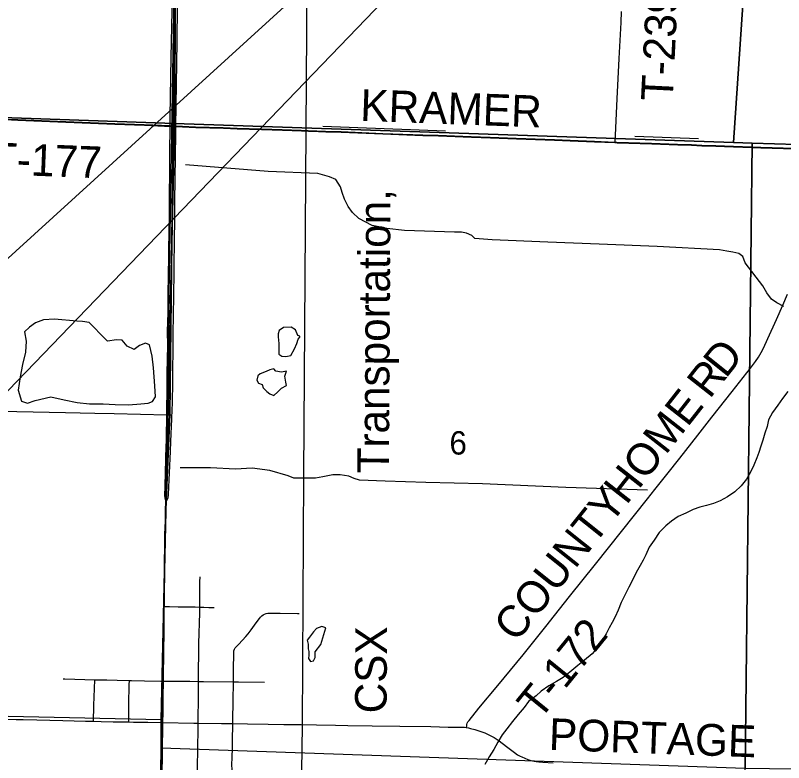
# Model space of a CAD drawing. Extents: x -59 to 43, y 0 to 22.
# Drawn here: x 24.882 to 26.258, y 14.155 to 15.494 of the extents above; entities that cross this region are included whole.
import ezdxf

# ---------------------------------------------------------------- set-up
doc = ezdxf.new("R2010")
doc.units = 0
for name, color, linetype in [('BR_P_Gen_Text', 7, 'Continuous'), ('Default', 7, 'Continuous'), ('GM_X_City_Street', 7, 'Continuous'), ('GM_X_Interchange_Ramps', 7, 'Continuous'), ('GM_X_Major_River', 7, 'Continuous'), ('GM_X_Minor_Lake', 7, 'Continuous'), ('GM_X_Minor_River', 7, 'Continuous'), ('GM_X_Rail_Line', 7, 'Continuous'), ('GM_X_Rail_Line_Text', 7, 'Continuous'), ('GM_X_Section', 7, 'Continuous'), ('GM_X_Section_Text', 7, 'Continuous'), ('GM_X_State_Route', 7, 'Continuous'), ('GM_X_Township_Road', 7, 'Continuous'), ('GM_X_Township_Road_Text', 7, 'Continuous')]:
    doc.layers.add(name, color=color, linetype=linetype)

msp = doc.modelspace()

# ---------------------------------------------------------------- linework, layer by layer
at = {"layer": 'BR_P_Gen_Text'}
msp.add_lwpolyline([(26.7273, 16.7521), (23.5585, 13.8664), (23.9482, 13.8664)], close=True, dxfattribs=at)
at = {"layer": 'Default'}
for points in [[(24.127, 14.1), (25.1417, 14.1), (25.1429, 14.1814), (25.1432, 14.2318), (24.1287, 14.2542)], [(25.1417, 14.1), (26.1878, 14.1), (26.1894, 14.1445), (25.1429, 14.1814)]]:
    msp.add_lwpolyline(points, close=True, dxfattribs=at)
at = {"layer": 'GM_X_City_Street'}
for points in [[(25.2095, 14.2261), (25.2095, 14.2286), (25.2094, 14.2365), (25.2096, 14.2485), (25.2097, 14.2548), (25.2098, 14.2625), (25.2099, 14.2686), (25.2099, 14.277), (25.2099, 14.2886), (25.2099, 14.2928), (25.21, 14.3008), (25.21, 14.3074), (25.2101, 14.3156), (25.2102, 14.3261), (25.2107, 14.3447), (25.2107, 14.3508), (25.2107, 14.3601), (25.2108, 14.3629), (25.2108, 14.3688), (25.2121, 14.4237), (25.2121, 14.433), (25.2121, 14.4338), (25.2122, 14.4391), (25.2121, 14.4422), (25.2124, 14.4607), (25.2125, 14.4678), (25.2126, 14.4792), (25.2127, 14.4881)], [(25.1484, 14.4352), (25.1581, 14.4349), (25.1735, 14.4345), (25.2042, 14.4341), (25.2121, 14.4338), (25.2196, 14.4336), (25.2287, 14.4334), (25.2348, 14.4332), (25.2378, 14.433)], [(25.2712, 14.2251), (25.2713, 14.2313), (25.2718, 14.2654), (25.2725, 14.2998), (25.2729, 14.3212), (25.2732, 14.3522), (25.2734, 14.3552), (25.2742, 14.3582), (25.2758, 14.3608), (25.2779, 14.3632), (25.282, 14.3677), (25.295, 14.381), (25.2989, 14.3858), (25.3046, 14.3931), (25.3134, 14.4059), (25.319, 14.4133), (25.321, 14.4157), (25.3232, 14.4179), (25.3257, 14.4198), (25.3284, 14.4212), (25.3313, 14.4221), (25.3344, 14.4227), (25.3406, 14.423), (25.3561, 14.423), (25.3871, 14.4223), (25.3902, 14.4222)], [(24.9673, 14.3053), (24.9703, 14.3053), (25.024, 14.3037), (25.0306, 14.3036), (25.0458, 14.3034), (25.064, 14.3031), (25.0862, 14.3025), (25.0902, 14.3024), (25.113, 14.3019), (25.1422, 14.3013), (25.1469, 14.3012)], [(25.0218, 14.2293), (25.0219, 14.2338), (25.0221, 14.2399), (25.0223, 14.2461), (25.0226, 14.2583), (25.023, 14.2724), (25.0235, 14.2882), (25.024, 14.3037)], [(25.085, 14.2281), (25.085, 14.2349), (25.0852, 14.2599), (25.086, 14.2943), (25.0862, 14.3025)], [(25.1469, 14.3012), (25.1751, 14.3011), (25.1942, 14.3009), (25.21, 14.3008), (25.2191, 14.3008), (25.2725, 14.2998), (25.2816, 14.2997), (25.328, 14.2993)], [(25.2086, 14.1095), (25.2085, 14.1156), (25.2084, 14.1217), (25.2084, 14.1248), (25.2084, 14.1433), (25.2083, 14.1489), (25.2083, 14.1512), (25.2083, 14.1585), (25.2086, 14.1677), (25.2087, 14.18), (25.2088, 14.1862), (25.2089, 14.1892), (25.2093, 14.2077), (25.2095, 14.2261)], [(25.2693, 14.1), (25.2695, 14.1014), (25.2698, 14.1056), (25.2699, 14.109), (25.27, 14.116), (25.2699, 14.1315), (25.27, 14.1438), (25.2699, 14.1505), (25.2699, 14.1537), (25.2701, 14.1623), (25.2708, 14.184), (25.2709, 14.1934), (25.2712, 14.2251)]]:
    msp.add_lwpolyline(points, dxfattribs=at)
at = {"layer": 'GM_X_Interchange_Ramps'}
for points in [[(24.8519, 15.3082), (24.886, 15.3068), (24.9574, 15.3039), (25.0599, 15.2995), (25.1127, 15.2977), (25.159, 15.2958), (25.1643, 15.2956), (25.1703, 15.7035), (25.1708, 15.7575), (25.1711, 15.7752), (25.1717, 15.8181), (25.1735, 16.0497), (25.1736, 16.0538), (25.1762, 16.1201), (25.1726, 16.298), (25.1734, 16.3535), (25.1731, 16.4049), (25.1737, 16.4832), (25.1737, 16.4888), (25.1743, 16.5339), (25.1743, 16.5397), (25.1751, 16.5992)], [(25.1703, 15.7035), (25.1643, 15.2956), (25.1692, 15.2953), (25.2047, 15.2938), (25.2544, 15.2923), (25.2793, 15.2914), (25.3228, 15.2898), (25.36, 15.2888), (25.3942, 15.2875), (25.4066, 15.287), (25.4376, 15.2859), (25.4656, 15.2851), (25.5402, 15.2819), (25.6116, 15.2795), (25.6396, 15.2784), (25.6986, 15.2765), (25.7328, 15.2753), (25.7794, 15.2732), (25.8477, 15.2708), (25.8757, 15.2698), (25.9192, 15.2681), (25.9561, 15.2664), (25.9596, 15.2663), (26.0217, 15.2644), (26.0683, 15.2628), (26.0932, 15.2617), (26.1118, 15.2609), (26.1367, 15.2601), (26.1522, 15.2596), (26.2174, 15.2572), (26.2982, 15.2549)], [(25.1448, 14.1524), (25.1451, 14.1725), (25.1457, 14.2277), (25.146, 14.2445), (25.1463, 14.2724), (25.1466, 14.3017), (25.1473, 14.3594), (25.1477, 14.3843), (25.1478, 14.3968), (25.1481, 14.4309), (25.1482, 14.4357), (25.1484, 14.4464), (25.1486, 14.4697), (25.1488, 14.4847), (25.1489, 14.4962), (25.1492, 14.521), (25.1494, 14.5367), (25.1496, 14.555), (25.1498, 14.567), (25.15, 14.5741), (25.1519, 14.6238), (25.1584, 14.7789), (25.159, 14.8311), (25.1643, 15.2956), (25.159, 15.2958), (25.1127, 15.2977), (25.0599, 15.2995), (24.9574, 15.3039), (24.886, 15.3068), (24.8519, 15.3082)], [(26.2982, 15.2549), (26.2174, 15.2572), (26.1522, 15.2596), (26.1367, 15.2601), (26.1118, 15.2609), (26.0932, 15.2617), (26.0683, 15.2628), (26.0217, 15.2644), (25.9596, 15.2663), (25.9561, 15.2664), (25.9192, 15.2681), (25.8757, 15.2698), (25.8477, 15.2708), (25.7794, 15.2732), (25.7328, 15.2753), (25.6986, 15.2765), (25.6396, 15.2784), (25.6116, 15.2795), (25.5402, 15.2819), (25.4656, 15.2851), (25.4376, 15.2859), (25.4066, 15.287), (25.3942, 15.2875), (25.36, 15.2888), (25.3228, 15.2898), (25.2793, 15.2914), (25.2544, 15.2923), (25.2047, 15.2938), (25.1692, 15.2953), (25.1643, 15.2956), (25.159, 14.8311), (25.1584, 14.7789), (25.1519, 14.6238), (25.15, 14.5741), (25.1498, 14.567), (25.1496, 14.555), (25.1494, 14.5367), (25.1492, 14.521), (25.1489, 14.4962), (25.1488, 14.4847), (25.1486, 14.4697), (25.1484, 14.4464), (25.1482, 14.4357), (25.1481, 14.4309), (25.1478, 14.3968), (25.1477, 14.3843), (25.1473, 14.3594), (25.1466, 14.3017), (25.1463, 14.2724), (25.146, 14.2445), (25.1457, 14.2277), (25.1451, 14.1725), (25.1448, 14.1524)]]:
    msp.add_lwpolyline(points, dxfattribs=at)
at = {"layer": 'GM_X_Major_River'}
msp.add_lwpolyline([(26.266, 14.8203), (26.2561, 14.8078), (26.2477, 14.7956), (26.2385, 14.7827), (26.2313, 14.7695), (26.2286, 14.7573), (26.2248, 14.7456), (26.2209, 14.7327), (26.2175, 14.7224), (26.214, 14.7106), (26.2106, 14.7011), (26.2052, 14.6879), (26.1991, 14.6757), (26.1915, 14.6628), (26.182, 14.6511), (26.1706, 14.6405), (26.1576, 14.6314), (26.1447, 14.6242), (26.1326, 14.6193), (26.1204, 14.6159), (26.1079, 14.6126), (26.0961, 14.6084), (26.0832, 14.6024), (26.0695, 14.596), (26.0573, 14.5876), (26.0471, 14.5797), (26.0356, 14.5672), (26.0261, 14.5539), (26.0174, 14.541), (26.0112, 14.5274), (26.0067, 14.5179), (26.0013, 14.5084), (25.9944, 14.4959), (25.988, 14.4834), (25.9811, 14.4693), (25.9738, 14.4553), (25.9673, 14.442), (25.962, 14.4284), (25.9563, 14.4162), (25.9513, 14.4064), (25.946, 14.3965), (25.9402, 14.3859), (25.9326, 14.3737), (25.9265, 14.3635), (25.9155, 14.3502), (25.9014, 14.3389), (25.8896, 14.3291), (25.8755, 14.3173), (25.8633, 14.3079), (25.8512, 14.3007), (25.8375, 14.2927), (25.8242, 14.2833), (25.8147, 14.2746), (25.8014, 14.2647), (25.7937, 14.2537), (25.7827, 14.2416), (25.7724, 14.2291), (25.7625, 14.2158), (25.7541, 14.2049), (25.7465, 14.1916), (25.7389, 14.1787), (25.7309, 14.1654), (25.7232, 14.1518)], dxfattribs=at)
at = {"layer": 'GM_X_Minor_Lake'}
for p, q in [((24.9922, 14.9463), (24.952, 14.9499)), ((25.3526, 14.9179), (25.3537, 14.9058)), ((25.3312, 14.8561), (25.3205, 14.8515)), ((25.4067, 14.359), (25.4078, 14.3544))]:
    msp.add_line(p, q, dxfattribs=at)
for points in [[(24.952, 14.9499), (24.9323, 14.9484), (24.9182, 14.9431), (24.9072, 14.9352), (24.8985, 14.9272), (24.9011, 14.9101), (24.8999, 14.8908), (24.8949, 14.8687), (24.8906, 14.8463), (24.8871, 14.8224), (24.8928, 14.803), (24.9038, 14.7992), (24.9174, 14.8041), (24.9455, 14.8108), (24.9694, 14.8051), (24.9926, 14.8005), (25.0149, 14.7981), (25.0392, 14.7977), (25.0605, 14.7968), (25.0847, 14.7964), (25.1068, 14.7982), (25.1197, 14.7993), (25.1273, 14.802), (25.133, 14.8103), (25.1315, 14.8301), (25.1293, 14.8623), (25.1268, 14.8836), (25.1223, 14.9038), (25.1151, 14.9068), (25.1044, 14.9023), (25.0945, 14.8955), (25.0824, 14.9012), (25.073, 14.9119), (25.0631, 14.9127), (25.0468, 14.9105), (25.0358, 14.9215), (25.0218, 14.936), (25.0139, 14.9436), (25.0021, 14.9455), (24.9922, 14.9463)], [(25.3537, 14.9058), (25.3537, 14.9004), (25.3537, 14.8936), (25.354, 14.8871), (25.3593, 14.8833), (25.3665, 14.8825), (25.3753, 14.8844), (25.3821, 14.8966), (25.386, 14.906), (25.3883, 14.9136), (25.3917, 14.9174), (25.3917, 14.9193), (25.3879, 14.9205), (25.3838, 14.9307), (25.3758, 14.9353), (25.3625, 14.9346), (25.3545, 14.9293), (25.3526, 14.9236), (25.3526, 14.9179)], [(25.3205, 14.8515), (25.316, 14.8481), (25.3144, 14.8402), (25.3175, 14.8348), (25.3239, 14.8325), (25.3258, 14.8264), (25.3322, 14.8203), (25.3379, 14.8158), (25.3447, 14.8131), (25.3519, 14.8195), (25.3588, 14.8263), (25.3679, 14.8309), (25.3664, 14.8366), (25.3645, 14.8476), (25.3676, 14.8563), (25.3589, 14.8548), (25.3483, 14.8568), (25.3452, 14.8606), (25.338, 14.8591), (25.3312, 14.8561)], [(25.4078, 14.3544), (25.4074, 14.3476), (25.407, 14.3419), (25.4108, 14.3362), (25.4161, 14.3377), (25.4191, 14.3433), (25.4192, 14.354), (25.4291, 14.3669), (25.4379, 14.3965), (25.4311, 14.3992), (25.4212, 14.3958), (25.4163, 14.3897), (25.409, 14.3802), (25.4048, 14.3749), (25.4067, 14.3677), (25.4067, 14.359)]]:
    msp.add_lwpolyline(points, dxfattribs=at)
at = {"layer": 'GM_X_Minor_River'}
for points in [[(25.6527, 15.2863), (25.4327, 15.2949)], [(26.1057, 15.2728), (25.9919, 15.277)], [(26.2585, 14.9726), (26.2463, 14.9787), (26.2365, 14.9852), (26.2282, 14.9967), (26.221, 15.0092), (26.1897, 15.0507), (26.1855, 15.0617), (26.1783, 15.0671), (26.1673, 15.0698), (26.1563, 15.0717), (26.1434, 15.074), (26.0315, 15.08), (25.9279, 15.0841), (25.8358, 15.0878), (25.7364, 15.0915), (25.7049, 15.0939), (25.6996, 15.0996), (25.6901, 15.1035), (25.681, 15.1054), (25.6685, 15.1058), (25.579, 15.1087), (25.5472, 15.112), (25.5213, 15.1172), (25.4974, 15.1299), (25.4861, 15.1405), (25.4782, 15.1516), (25.4714, 15.1649), (25.4672, 15.1767), (25.4646, 15.1869), (25.4563, 15.1999), (25.4449, 15.2045), (25.4362, 15.2072), (25.4237, 15.2106), (25.3345, 15.2139), (25.1866, 15.2261)], [(26.0143, 14.6436), (25.8682, 14.6482), (25.7187, 14.6547), (25.6174, 14.6573), (25.5442, 14.6594), (25.4987, 14.6611), (25.4888, 14.6645), (25.4793, 14.6683), (25.4638, 14.671), (25.4509, 14.6707), (25.433, 14.6673), (25.4194, 14.6647), (25.4, 14.6648), (25.3807, 14.6648), (25.3704, 14.669), (25.3375, 14.6786), (25.3064, 14.6825), (25.2764, 14.6811), (25.2316, 14.6835), (25.1774, 14.6833)]]:
    msp.add_lwpolyline(points, dxfattribs=at)
at = {"layer": 'GM_X_Rail_Line'}
for points in [[(25.3948, 14.1), (25.3961, 14.2211), (25.3988, 14.6701), (25.4079, 15.9972), (25.4144, 16.3516), (25.419, 16.4865), (25.4235, 16.5443), (25.4371, 16.6599), (25.4762, 17.0572), (25.4837, 17.1373), (25.4914, 17.219), (25.4936, 17.2735), (25.4946, 17.3274), (25.4973, 17.5422), (25.5003, 17.9438), (25.5067, 18.4239), (25.5079, 18.556), (25.5143, 18.6352), (25.5252, 18.7035), (25.5418, 18.7744), (25.5673, 18.8657), (25.6145, 19.001)], [(25.1428, 14.1), (25.1449, 14.2295), (25.1538, 14.7802), (25.1709, 15.8209), (25.1663, 16.5615), (25.1883, 17.5646)]]:
    msp.add_lwpolyline(points, dxfattribs=at)
at = {"layer": 'GM_X_Section'}
for points in [[(24.1477, 16.3396), (25.173, 16.308), (25.1744, 16.294), (25.1667, 15.3001), (24.1557, 15.3353)], [(25.1744, 16.294), (26.2361, 16.2622), (26.1685, 15.2661), (25.1667, 15.3001)], [(26.2361, 16.2622), (27.2374, 16.2454), (27.2021, 15.2348), (26.2022, 15.2649), (26.1685, 15.2661)], [(24.1557, 15.3353), (25.1667, 15.3001), (25.1432, 14.2318), (24.1287, 14.2542)], [(25.1667, 15.3001), (26.1685, 15.2661), (26.2022, 15.2649), (26.1894, 14.1445), (25.1429, 14.1814), (25.1432, 14.2318)], [(26.2022, 15.2649), (27.2021, 15.2348), (27.2112, 15.2343), (27.188, 14.1311), (26.1894, 14.1445)]]:
    msp.add_lwpolyline(points, close=True, dxfattribs=at)
at = {"layer": 'GM_X_State_Route'}
msp.add_line((25.1532, 14.7785), (25.154, 14.8322), dxfattribs=at)
for points in [[(25.1592, 15.2952), (25.1594, 15.3126), (25.1612, 15.4182), (25.1626, 15.5021), (25.1627, 15.5301), (25.1629, 15.5394), (25.1635, 15.5609), (25.1641, 15.6138), (25.1642, 15.6293), (25.1653, 15.6821), (25.1656, 15.7008), (25.1656, 15.703)], [(25.1694, 15.2948), (25.1715, 15.4466), (25.1723, 15.5118), (25.1737, 15.6113), (25.1741, 15.6485), (25.1745, 15.6734), (25.175, 15.6951), (25.175, 15.7029)], [(25.154, 14.8322), (25.1541, 14.8371), (25.1541, 14.8527), (25.1549, 14.9024), (25.1546, 14.9273), (25.1554, 14.9614), (25.1559, 15.0049), (25.1561, 15.0173), (25.1571, 15.0733), (25.1578, 15.1385), (25.1587, 15.2473), (25.1592, 15.2952)], [(25.1637, 14.8308), (25.1642, 14.8562), (25.1643, 14.8966), (25.1648, 14.9214), (25.1654, 14.9587), (25.1657, 14.9898), (25.1662, 15.0364), (25.1672, 15.0985), (25.1676, 15.1203), (25.1678, 15.1607), (25.1692, 15.2819), (25.1694, 15.2948)], [(25.1621, 14.7712), (25.1624, 14.7783), (25.1625, 14.7808), (25.1637, 14.8308)], [(25.1522, 14.6232), (25.1539, 14.6259), (25.1554, 14.6301), (25.156, 14.6336), (25.1563, 14.6363), (25.1597, 14.7128), (25.1603, 14.7307), (25.1621, 14.7712)], [(25.1524, 14.7303), (25.1525, 14.7358), (25.1532, 14.7785)], [(25.1522, 14.6232), (25.1506, 14.6268), (25.15, 14.6296), (25.1497, 14.6333), (25.1504, 14.6505), (25.1522, 14.7232), (25.1524, 14.7303)], [(25.1481, 14.3992), (25.1483, 14.4304), (25.1484, 14.4352), (25.1486, 14.4459), (25.1489, 14.4691), (25.149, 14.4842), (25.1491, 14.4957), (25.1494, 14.5205), (25.1496, 14.5362), (25.1498, 14.5545), (25.15, 14.5664), (25.1502, 14.5736), (25.1522, 14.6232)], [(25.147, 14.3131), (25.1476, 14.3589), (25.1479, 14.3837), (25.1481, 14.3962), (25.1481, 14.3992)], [(25.1459, 14.2272), (25.1462, 14.2439), (25.1465, 14.2718), (25.1469, 14.3012), (25.147, 14.3131)], [(25.1442, 14.1), (25.1446, 14.1244), (25.1449, 14.1438), (25.145, 14.1518), (25.1453, 14.1719), (25.1459, 14.2272)]]:
    msp.add_lwpolyline(points, dxfattribs=at)
at = {"layer": 'GM_X_Township_Road'}
for p, q in [((25.1492, 15.2957), (25.1592, 15.2952)), ((25.1592, 15.2952), (25.1646, 15.295)), ((25.1646, 15.295), (25.1694, 15.2948)), ((25.1586, 14.7784), (25.1624, 14.7783))]:
    msp.add_line(p, q, dxfattribs=at)
for points in [[(25.9564, 15.2659), (25.9565, 15.2691), (25.957, 15.2795), (25.9602, 15.3442), (25.9639, 15.4168), (25.9671, 15.4814), (25.9681, 15.5007)], [(24.154, 15.3313), (24.1784, 15.3306), (24.2405, 15.3285), (24.2995, 15.3269), (24.3554, 15.3253), (24.3927, 15.3239), (24.4734, 15.3211), (24.5386, 15.3187), (24.6163, 15.3158), (24.6565, 15.3141), (24.6936, 15.313), (24.7682, 15.3106), (24.8117, 15.309), (24.8521, 15.3077), (24.8862, 15.3063), (24.9577, 15.3034), (25.0601, 15.299), (25.113, 15.2972), (25.1492, 15.2957)], [(25.1694, 15.2948), (25.2049, 15.2932), (25.2546, 15.2918), (25.2795, 15.2909), (25.323, 15.2892), (25.3603, 15.2883), (25.3944, 15.2869), (25.4068, 15.2864), (25.4118, 15.2863)], [(25.4118, 15.2863), (25.4379, 15.2854), (25.4658, 15.2845), (25.5404, 15.2814), (25.6119, 15.2789), (25.6398, 15.2778), (25.6989, 15.2759), (25.733, 15.2748), (25.7796, 15.2727), (25.848, 15.2703), (25.8759, 15.2692), (25.9194, 15.2675), (25.9564, 15.2659)], [(25.9564, 15.2659), (25.9598, 15.2657), (26.0219, 15.2638), (26.0686, 15.2622), (26.0934, 15.2611), (26.112, 15.2604), (26.1369, 15.2596), (26.1524, 15.2591), (26.2176, 15.2567), (26.2984, 15.2544), (26.3085, 15.2542)], [(25.6903, 14.218), (25.6905, 14.2213), (25.6908, 14.2235), (25.6915, 14.2257), (25.6928, 14.2285), (25.6947, 14.2309), (25.7124, 14.2525), (25.7461, 14.2932), (25.7916, 14.3482), (25.8325, 14.3991), (25.8478, 14.4186), (25.8746, 14.4528), (25.9213, 14.511), (25.9446, 14.54), (25.9911, 14.5983), (26.0142, 14.6275), (26.0277, 14.6445), (26.0491, 14.6712), (26.0721, 14.7005), (26.1048, 14.7419), (26.1296, 14.7738), (26.1661, 14.8202), (26.1988, 14.8616), (26.2081, 14.8741), (26.2133, 14.8818), (26.2181, 14.8898), (26.2224, 14.898), (26.2302, 14.9149), (26.2453, 14.949), (26.2566, 14.9746), (26.2654, 14.9945)], [(24.6465, 14.7869), (24.6525, 14.7877), (24.661, 14.7881), (24.6765, 14.7879), (24.7387, 14.7867), (24.7884, 14.7862), (24.8195, 14.7855), (24.8443, 14.785), (24.8847, 14.7842), (24.9717, 14.7825), (25.0245, 14.7814), (25.0587, 14.7808), (25.1532, 14.7785)], [(25.1532, 14.7785), (25.1574, 14.7784), (25.1586, 14.7784)], [(24.6959, 14.2348), (24.7249, 14.2342), (24.7902, 14.2334), (24.8306, 14.2332), (24.8834, 14.2326), (24.8958, 14.2322), (24.9206, 14.2317), (24.9671, 14.2306), (25.0075, 14.2297), (25.0218, 14.2293)], [(25.0218, 14.2293), (25.0355, 14.2289), (25.0572, 14.2285), (25.085, 14.2281)], [(25.085, 14.2281), (25.0938, 14.2279), (25.1194, 14.2275), (25.1459, 14.2272)], [(25.1459, 14.2272), (25.2015, 14.2262), (25.2095, 14.2261)], [(25.2095, 14.2261), (25.2511, 14.2254), (25.2712, 14.2251)], [(25.2712, 14.2251), (25.2976, 14.2246), (25.3348, 14.2241), (25.3627, 14.2237), (25.3937, 14.2233), (25.4216, 14.2229), (25.4557, 14.2221), (25.4774, 14.2218), (25.5209, 14.2212), (25.5705, 14.2206), (25.6263, 14.2198), (25.6573, 14.219), (25.6761, 14.2187)], [(25.6761, 14.2187), (25.6821, 14.2188), (25.6865, 14.2185), (25.6894, 14.2181), (25.6903, 14.218)], [(25.6903, 14.218), (25.6937, 14.2174), (25.6975, 14.2165), (25.7052, 14.2143), (25.7142, 14.2116), (25.723, 14.2084), (25.7316, 14.2045), (25.7398, 14.2), (25.7485, 14.194), (25.7619, 14.1839), (25.7762, 14.1731), (25.7818, 14.1692), (25.786, 14.1669), (25.789, 14.1654), (25.7944, 14.1631), (25.7999, 14.1609), (25.8054, 14.1593), (25.8113, 14.1578), (25.8149, 14.1571), (25.8199, 14.1564), (25.8266, 14.1558), (25.8452, 14.1548)]]:
    msp.add_lwpolyline(points, dxfattribs=at)

# ---------------------------------------------------------------- texts
at = {"layer": 'GM_X_Rail_Line_Text'}
for s, height, rotation, p in [('Transportation,', 0.056629, 89.6638, (25.551, 14.6732)), ('CSX', 0.05663, 89.7349, (25.547, 14.2434))]:
    msp.add_text(s, height=height, rotation=rotation, dxfattribs=at).set_placement(p)
at = {"layer": 'GM_X_Section_Text'}
msp.add_text('6', height=0.0419, rotation=0, dxfattribs=at).set_placement((25.6596, 14.7071))
at = {"layer": 'GM_X_Township_Road_Text'}
for s, height, rotation, p in [('T-239', 0.05682, 87.1962, (26.0594, 15.3394)), ('KRAMER', 0.05682, 357.9201, (25.4991, 15.3049)), ('T-177', 0.05682, 357.7543, (24.8372, 15.2097)), ('D', 0.0568, 51.487, (26.1546, 14.842)), ('R', 0.0568, 51.8412, (26.1258, 14.8054)), ('HOME', 0.05682, 51.8926, (25.9766, 14.6154)), ('COUNTY', 0.05682, 51.4175, (25.7792, 14.3688)), ('T-172', 0.05682, 50.9458, (25.8209, 14.2294)), ('PORTAGE', 0.05682, 357.9285, (25.837, 14.1781))]:
    msp.add_text(s, height=height, rotation=rotation, dxfattribs=at).set_placement(p)

doc.saveas('drawing.dxf')
